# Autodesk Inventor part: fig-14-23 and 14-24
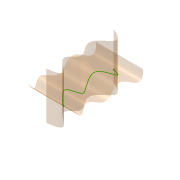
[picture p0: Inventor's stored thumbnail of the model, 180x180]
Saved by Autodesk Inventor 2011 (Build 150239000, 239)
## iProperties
Created: 2007-05
Part Number: fig-14-23 and 14-24
Document SubType Name: Modeling
Designer: Administrator
Density: 1 g/cm^3
Author: Administrator
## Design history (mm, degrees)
node "Sketch1"
node "Sketch2"
sketch "Sketch3"
  geometry: 7 further points
  constraints: 7 other
extrude_surface "ExtrusionSrf1" sketch "Sketch3" dims "d0" = 50, "d1" = 0
sketch "Sketch4"
  geometry: 7 further points
  constraints: 7 other
extrude_surface "ExtrusionSrf2" sketch "Sketch4" dims "d2" = 50, "d3" = 0
sketch "3D Sketch1"
  node "3D Intersection1"
body "Srf1"
body "Srf2"
